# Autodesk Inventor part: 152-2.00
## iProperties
Created: 2007-06
Part Number: 152-2.00
Document SubType Name: Modeling
Designer: btaylor
Density: 1 g/cm^3
Author: btaylor
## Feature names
1. Sweep1
2. Extrusion1
3. Extrusion2
4. Fillet1
5. Fillet2
6. Extrusion3
7. Chamfer1
8. Fillet3
9. Chamfer2
10. Sweep2
11. Fillet4
12. Fillet5
13. Fillet6
